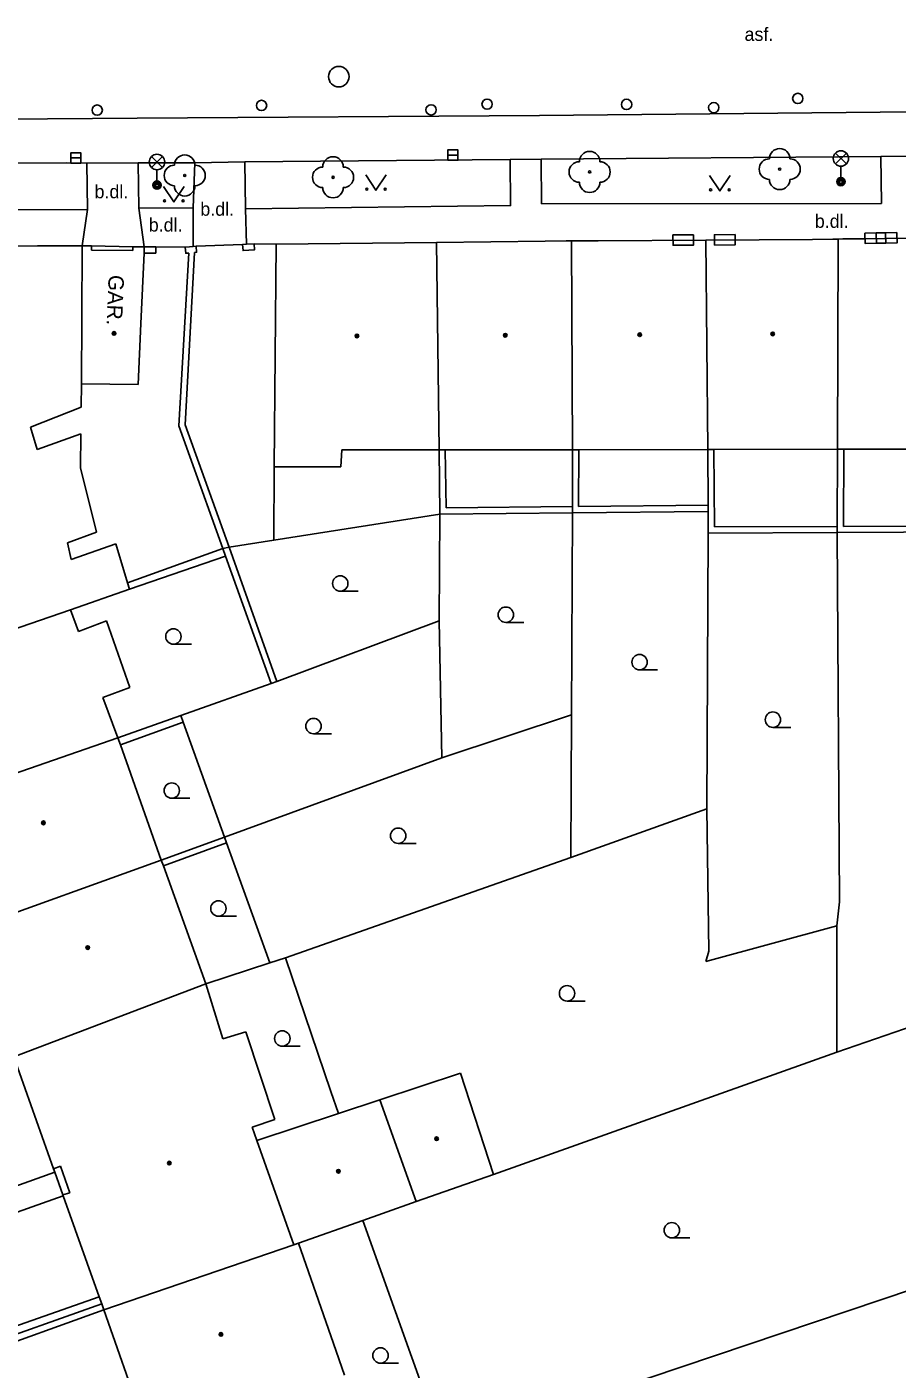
# Model space of a CAD drawing. Extents: x -596229 to -595156, y -1161237 to -1159376.
# Drawn here: x -595936.1 to -595893.7, y -1160957.9 to -1160892.5 of the extents above; entities that cross this region are included whole.
import ezdxf

# ---------------------------------------------------------------- set-up
doc = ezdxf.new("R2010")
doc.units = 0
for name, color, linetype in [('DOP - kresba z DSPS bez souradnic', 7, 'Continuous'), ('DOP - ploty', 7, 'Continuous'), ('DOP - rozhrani ploch obecne', 7, 'Continuous'), ('Level 22', 7, 'Continuous'), ('Level 24', 7, 'Continuous'), ('Level 27', 7, 'Continuous'), ('Level 28', 7, 'Continuous'), ('Level 33', 7, 'Continuous'), ('Level 36', 7, 'Continuous'), ('Level 39', 7, 'Continuous'), ('TM - budovy zdene_ betonove - NP', 7, 'Continuous'), ('TM - budovy zdene_ betonove - VP', 7, 'Continuous'), ('TM - chodniky - VP', 7, 'Continuous'), ('TM - komunikace - VP', 7, 'Continuous'), ('TM - letecke snimky - pomocna linie', 7, 'Continuous'), ('TM - plot drateny_ kovovy - VP', 7, 'Continuous'), ('TM - podezdivka plotu - VP', 7, 'Continuous'), ('TM - popis objektu', 7, 'Continuous'), ('TM - popis povrchu', 7, 'Continuous'), ('TM - rozhrani ploch obecne - VP', 7, 'Continuous'), ('TM - vjezd na pozemek', 7, 'Continuous'), ('TM - vstup do budovy - zdene_ betonove', 7, 'Continuous'), ('TM - vstup do budovy - zdene_ betonove  - shora neviditelny', 7, 'Continuous')]:
    doc.layers.add(name, color=color, linetype=linetype)

msp = doc.modelspace()

# ---------------------------------------------------------------- linework, layer by layer
at = {"layer": 'DOP - kresba z DSPS bez souradnic'}
for points in [[(-595926.56, -1160917.92), (-595931.2, -1160919.6)], [(-595931.55, -1160927.48), (-595928.5, -1160926.38)], [(-595929.46, -1160933.38), (-595926.38, -1160932.26)]]:
    msp.add_lwpolyline(points, dxfattribs=at)
at = {"layer": 'DOP - ploty'}
for points in [[(-595903, -1160930.6), (-595909.62, -1160932.97)], [(-595902.91, -1160937.53), (-595903, -1160930.6)], [(-595909.62, -1160932.97), (-595923.51, -1160937.85)], [(-595896.67, -1160936.29), (-595903.05, -1160938.03)], [(-595896.68, -1160942.44), (-595896.67, -1160936.29)], [(-595923.51, -1160937.85), (-595924.27, -1160938.1)], [(-595903.05, -1160938.03), (-595902.91, -1160937.53)], [(-595924.27, -1160938.1), (-595927.39, -1160939.12)], [(-595896.68, -1160942.44), (-595913.39, -1160948.39)]]:
    msp.add_lwpolyline(points, dxfattribs=at)
at = {"layer": 'DOP - rozhrani ploch obecne'}
for points in [[(-595916, -1160916.25), (-595924.09, -1160917.53)], [(-595916, -1160916.25), (-595916.03, -1160921.45)], [(-595909.59, -1160926.02), (-595909.55, -1160916.19)], [(-595896.54, -1160935.13), (-595896.66, -1160917.15)], [(-595924.09, -1160917.53), (-595926.26, -1160917.87)], [(-595903, -1160930.6), (-595902.94, -1160917.18)], [(-595926.43, -1160918.3), (-595931.1, -1160919.91)], [(-595926.26, -1160917.87), (-595926.56, -1160917.92)], [(-595916.03, -1160921.45), (-595923.93, -1160924.4)], [(-595915.9, -1160928.12), (-595916.03, -1160921.45)], [(-595924.21, -1160924.5), (-595928.61, -1160926.06)], [(-595923.93, -1160924.4), (-595924.21, -1160924.5)], [(-595928.61, -1160926.06), (-595931.67, -1160927.14)], [(-595928.61, -1160926.06), (-595928.5, -1160926.38)], [(-595915.9, -1160928.12), (-595909.59, -1160926.02)], [(-595909.62, -1160932.97), (-595909.59, -1160926.02)], [(-595928.5, -1160926.38), (-595926.48, -1160931.98)], [(-595926.48, -1160931.98), (-595915.9, -1160928.12)], [(-595926.48, -1160931.98), (-595929.56, -1160933.1)], [(-595926.38, -1160932.26), (-595926.48, -1160931.98)], [(-595924.27, -1160938.1), (-595926.38, -1160932.26)], [(-595896.67, -1160936.29), (-595896.54, -1160935.13)], [(-595921.3, -1160944.36), (-595923.51, -1160937.85)], [(-595896.68, -1160942.44), (-595890.09, -1160940.17)], [(-595920.94, -1160945.43), (-595921.3, -1160944.36)], [(-595915.78, -1160961.75), (-595919.75, -1160950.64)], [(-595889.72, -1160952.88), (-595909.04, -1160959.39)]]:
    msp.add_lwpolyline(points, dxfattribs=at)
at = {"layer": 'Level 22'}
for centre in [(-595899.46, -1160899.46), (-595928.42, -1160899.77), (-595921.2, -1160899.86), (-595908.71, -1160899.6)]:
    msp.add_circle(centre, 0.05, dxfattribs=at)
for centre, start, end in [((-595928.42, -1160899.27), 0, 180), ((-595921.2, -1160899.36), 0, 180), ((-595908.71, -1160899.1), 0, 180), ((-595899.46, -1160898.96), 0, 180), ((-595928.92, -1160899.77), 90, 270), ((-595927.92, -1160899.77), 270, 90), ((-595921.7, -1160899.86), 90, 270), ((-595920.7, -1160899.86), 270, 90), ((-595909.21, -1160899.6), 90, 270), ((-595908.21, -1160899.6), 270, 90), ((-595899.96, -1160899.46), 90, 270), ((-595898.96, -1160899.46), 270, 90), ((-595908.71, -1160900.1), 180, 0), ((-595899.46, -1160899.96), 180, 0), ((-595928.42, -1160900.27), 180, 0), ((-595921.2, -1160900.36), 180, 0)]:
    msp.add_arc(centre, 0.5, start, end, dxfattribs=at)
at = {"layer": 'Level 24'}
for points in [[(-595903.653, -1160902.658), (-595904.653, -1160902.664), (-595904.65, -1160903.164), (-595903.65, -1160903.158)], [(-595901.634, -1160902.647), (-595902.634, -1160902.655), (-595902.63, -1160903.155), (-595901.63, -1160903.147)], [(-595894.307, -1160902.565), (-595895.307, -1160902.58), (-595895.299, -1160903.08), (-595894.299, -1160903.065)], [(-595893.756, -1160902.553), (-595894.756, -1160902.569), (-595894.748, -1160903.069), (-595893.748, -1160903.053)]]:
    msp.add_lwpolyline(points, close=True, dxfattribs=at)
at = {"layer": 'Level 27'}
for p, q in [((-595915.62, -1160898.78), (-595915.12, -1160898.78)), ((-595933.97, -1160898.92), (-595933.47, -1160898.92))]:
    msp.add_line(p, q, dxfattribs=at)
for points in [[(-595933.97, -1160899.17), (-595933.47, -1160899.17), (-595933.47, -1160898.67), (-595933.97, -1160898.67)], [(-595915.62, -1160899.03), (-595915.12, -1160899.03), (-595915.12, -1160898.53), (-595915.62, -1160898.53)]]:
    msp.add_lwpolyline(points, close=True, dxfattribs=at)
msp.add_circle((-595920.92, -1160894.96), 0.5, dxfattribs=at)
at = {"layer": 'Level 28'}
for centre in [(-595924.68, -1160896.36), (-595913.7, -1160896.3), (-595906.91, -1160896.31), (-595902.67, -1160896.47), (-595898.58, -1160896.02), (-595932.68, -1160896.59), (-595916.43, -1160896.58)]:
    msp.add_circle(centre, 0.25, dxfattribs=at)
at = {"layer": 'Level 33'}
for p, q in [((-595930.035, -1160899.38), (-595929.505, -1160898.85)), ((-595930.035, -1160898.85), (-595929.505, -1160899.38)), ((-595896.745, -1160899.21), (-595896.215, -1160898.68)), ((-595896.745, -1160898.68), (-595896.215, -1160899.21)), ((-595929.77, -1160899.49), (-595929.77, -1160900.24)), ((-595896.48, -1160899.32), (-595896.48, -1160900.07))]:
    msp.add_line(p, q, dxfattribs=at)
for centre, radius in [((-595929.77, -1160899.115), 0.375), ((-595896.48, -1160898.945), 0.375), ((-595929.77, -1160900.24), 0.2), ((-595929.77, -1160900.24), 0.145), ((-595929.77, -1160900.24), 0.0876), ((-595896.48, -1160900.07), 0.2), ((-595896.48, -1160900.07), 0.145), ((-595896.48, -1160900.07), 0.0876)]:
    msp.add_circle(centre, radius, dxfattribs=at)
at = {"layer": 'Level 36'}
for p, q in [((-595920.85, -1160920.005), (-595919.975, -1160920.005)), ((-595912.79, -1160921.525), (-595911.915, -1160921.525)), ((-595928.97, -1160922.585), (-595928.095, -1160922.585)), ((-595906.28, -1160923.835), (-595905.405, -1160923.835)), ((-595922.15, -1160926.945), (-595921.275, -1160926.945)), ((-595899.79, -1160926.635), (-595898.915, -1160926.635)), ((-595929.05, -1160930.085), (-595928.175, -1160930.085)), ((-595918.03, -1160932.285), (-595917.155, -1160932.285)), ((-595926.78, -1160935.825), (-595925.905, -1160935.825)), ((-595909.81, -1160939.955), (-595908.935, -1160939.955)), ((-595923.67, -1160942.155), (-595922.795, -1160942.155)), ((-595904.71, -1160951.485), (-595903.835, -1160951.485)), ((-595918.89, -1160957.585), (-595918.015, -1160957.585))]:
    msp.add_line(p, q, dxfattribs=at)
for points in [[(-595919.61, -1160899.74), (-595919.11, -1160900.49), (-595918.61, -1160899.74)], [(-595902.87, -1160899.77), (-595902.37, -1160900.52), (-595901.87, -1160899.77)], [(-595929.45, -1160900.31), (-595928.95, -1160901.06), (-595928.45, -1160900.31)]]:
    msp.add_lwpolyline(points, dxfattribs=at)
for centre, radius in [((-595919.56, -1160900.44), 0.05), ((-595918.661, -1160900.44), 0.05), ((-595902.82, -1160900.47), 0.05), ((-595901.921, -1160900.47), 0.05), ((-595929.4, -1160901.01), 0.05), ((-595928.501, -1160901.01), 0.05), ((-595920.85, -1160919.63), 0.375), ((-595912.79, -1160921.15), 0.375), ((-595928.97, -1160922.21), 0.375), ((-595906.28, -1160923.46), 0.375), ((-595922.15, -1160926.57), 0.375), ((-595899.79, -1160926.26), 0.375), ((-595929.05, -1160929.71), 0.375), ((-595918.03, -1160931.91), 0.375), ((-595926.78, -1160935.45), 0.375), ((-595909.81, -1160939.58), 0.375), ((-595923.67, -1160941.78), 0.375), ((-595904.71, -1160951.11), 0.375), ((-595918.89, -1160957.21), 0.375)]:
    msp.add_circle(centre, radius, dxfattribs=at)
at = {"layer": 'Level 39'}
for centre, radius in [((-595931.86, -1160907.46), 0.09), ((-595931.86, -1160907.46), 0.0398), ((-595920.04, -1160907.58), 0.09), ((-595920.04, -1160907.58), 0.0398), ((-595912.82, -1160907.55), 0.09), ((-595912.82, -1160907.55), 0.0398), ((-595906.27, -1160907.52), 0.09), ((-595906.27, -1160907.52), 0.0398), ((-595899.8, -1160907.48), 0.09), ((-595899.8, -1160907.48), 0.0398), ((-595935.3, -1160931.28), 0.09), ((-595935.3, -1160931.28), 0.0398), ((-595933.14, -1160937.35), 0.09), ((-595933.14, -1160937.35), 0.0398), ((-595916.16, -1160946.66), 0.09), ((-595916.16, -1160946.66), 0.0398), ((-595929.17, -1160947.84), 0.09), ((-595929.17, -1160947.84), 0.0398), ((-595920.94, -1160948.24), 0.09), ((-595920.94, -1160948.24), 0.0398), ((-595926.66, -1160956.18), 0.09), ((-595926.66, -1160956.18), 0.0398)]:
    msp.add_circle(centre, radius, dxfattribs=at)
at = {"layer": 'TM - budovy zdene_ betonove - NP'}
for points in [[(-595932.95, -1160903.2), (-595932.95, -1160903.41)], [(-595930.94, -1160903.42), (-595930.94, -1160903.24)], [(-595934.47, -1160948), (-595934.8, -1160948.12)], [(-595934.02, -1160949.29), (-595934.47, -1160948)], [(-595934.02, -1160949.29), (-595934.35, -1160949.39)]]:
    msp.add_lwpolyline(points, dxfattribs=at)
at = {"layer": 'TM - budovy zdene_ betonove - VP'}
for points in [[(-595895.33, -1160902.85), (-595890.07, -1160902.77)], [(-595942.44, -1160903.23), (-595935.58, -1160903.2)], [(-595935.58, -1160903.2), (-595934.62, -1160903.2)], [(-595934.62, -1160903.2), (-595933.42, -1160903.19)], [(-595933.42, -1160903.19), (-595933.43, -1160906.67)], [(-595933.42, -1160903.19), (-595932.95, -1160903.2)], [(-595932.95, -1160903.2), (-595930.94, -1160903.24)], [(-595930.94, -1160903.24), (-595930.39, -1160903.25)], [(-595930.39, -1160903.25), (-595930.4, -1160903.55)], [(-595924.06, -1160913.96), (-595923.97, -1160903.12)], [(-595923.97, -1160903.12), (-595916.16, -1160903.03)], [(-595916.16, -1160903.03), (-595910.88, -1160902.97)], [(-595916.16, -1160903.03), (-595916.04, -1160913.12)], [(-595909.86, -1160902.96), (-595909.59, -1160902.96)], [(-595909.59, -1160902.96), (-595909.55, -1160913.12)], [(-595909.59, -1160902.96), (-595909.34, -1160902.96)], [(-595908.3, -1160902.95), (-595903.06, -1160902.92)], [(-595903.06, -1160902.92), (-595897.86, -1160902.88)], [(-595902.96, -1160913.11), (-595903.06, -1160902.92)], [(-595896.87, -1160902.87), (-595896.62, -1160902.87)], [(-595896.62, -1160902.87), (-595896.64, -1160913.1)], [(-595896.62, -1160902.87), (-595896.38, -1160902.86)], [(-595930.4, -1160903.55), (-595930.56, -1160906.98)], [(-595933.43, -1160906.67), (-595933.45, -1160909.91)], [(-595930.56, -1160906.98), (-595930.69, -1160909.94)], [(-595933.45, -1160909.91), (-595933.46, -1160911.05)], [(-595930.69, -1160909.94), (-595933.45, -1160909.91)], [(-595933.46, -1160911.05), (-595935.93, -1160912.02)], [(-595935.93, -1160912.02), (-595935.6, -1160913.11)], [(-595935.6, -1160913.11), (-595933.48, -1160912.35)], [(-595933.48, -1160912.35), (-595933.49, -1160914)], [(-595920.77, -1160913.13), (-595920.82, -1160913.96)], [(-595916.04, -1160913.12), (-595920.77, -1160913.13)], [(-595915.74, -1160913.12), (-595916.04, -1160913.12)], [(-595909.55, -1160913.12), (-595915.74, -1160913.12)], [(-595909.23, -1160913.12), (-595909.55, -1160913.12)], [(-595902.96, -1160913.11), (-595909.23, -1160913.12)], [(-595902.66, -1160913.11), (-595902.96, -1160913.11)], [(-595896.64, -1160913.1), (-595902.66, -1160913.11)], [(-595896.34, -1160913.1), (-595896.64, -1160913.1)], [(-595890.18, -1160913.09), (-595896.34, -1160913.1)], [(-595933.49, -1160914), (-595932.72, -1160917.14)], [(-595920.82, -1160913.96), (-595924.06, -1160913.96)], [(-595932.72, -1160917.14), (-595934.12, -1160917.65)], [(-595934.12, -1160917.65), (-595933.94, -1160918.46)], [(-595933.94, -1160918.46), (-595931.78, -1160917.7)], [(-595931.78, -1160917.7), (-595931.2, -1160919.6)], [(-595931.2, -1160919.6), (-595931.1, -1160919.91)], [(-595931.1, -1160919.91), (-595933.98, -1160920.91)], [(-595933.98, -1160920.91), (-595943.32, -1160924.13)], [(-595933.98, -1160920.91), (-595933.59, -1160921.96)], [(-595933.59, -1160921.96), (-595932.22, -1160921.45)], [(-595932.22, -1160921.45), (-595931.09, -1160924.7)], [(-595931.09, -1160924.7), (-595932.4, -1160925.18)], [(-595932.4, -1160925.18), (-595931.67, -1160927.14)], [(-595931.67, -1160927.14), (-595941.09, -1160930.4)], [(-595931.67, -1160927.14), (-595931.55, -1160927.48)], [(-595931.55, -1160927.48), (-595929.56, -1160933.1)], [(-595929.56, -1160933.1), (-595938.94, -1160936.48)], [(-595929.56, -1160933.1), (-595929.46, -1160933.38)], [(-595929.46, -1160933.38), (-595927.39, -1160939.12)], [(-595936.74, -1160942.67), (-595927.39, -1160939.12)], [(-595927.39, -1160939.12), (-595926.57, -1160941.8)], [(-595926.57, -1160941.8), (-595925.44, -1160941.46)], [(-595925.44, -1160941.46), (-595924.04, -1160945.72)], [(-595934.8, -1160948.12), (-595936.74, -1160942.67)], [(-595918.92, -1160944.76), (-595915, -1160943.47)], [(-595915, -1160943.47), (-595913.39, -1160948.39)], [(-595920.94, -1160945.43), (-595918.92, -1160944.76)], [(-595917.16, -1160949.72), (-595918.92, -1160944.76)], [(-595924.04, -1160945.72), (-595925.14, -1160946.1)], [(-595924.91, -1160946.75), (-595920.94, -1160945.43)], [(-595925.14, -1160946.1), (-595924.91, -1160946.75)], [(-595924.91, -1160946.75), (-595923.11, -1160951.82)], [(-595934.74, -1160948.28), (-595934.8, -1160948.12)], [(-595934.35, -1160949.39), (-595934.74, -1160948.28)], [(-595913.39, -1160948.39), (-595917.16, -1160949.72)], [(-595934.33, -1160949.44), (-595934.35, -1160949.39)], [(-595932.58, -1160954.36), (-595934.33, -1160949.44)], [(-595917.16, -1160949.72), (-595918.8, -1160950.3), (-595919.75, -1160950.64)], [(-595919.75, -1160950.64), (-595922.88, -1160951.74)], [(-595922.88, -1160951.74), (-595923.11, -1160951.82)], [(-595922.88, -1160951.74), (-595921.18, -1160956.63), (-595920.65, -1160958.16)], [(-595923.11, -1160951.82), (-595932.36, -1160954.98)], [(-595932.46, -1160954.7), (-595932.58, -1160954.36)], [(-595932.36, -1160954.98), (-595932.46, -1160954.7)], [(-595930.49, -1160960.3), (-595932.36, -1160954.98)]]:
    msp.add_lwpolyline(points, dxfattribs=at)
at = {"layer": 'TM - chodniky - VP'}
for points in [[(-595894.53, -1160898.84), (-595894.51, -1160901.13), (-595911.05, -1160901.15), (-595911.07, -1160898.98)], [(-595933.16, -1160901.42), (-595942.46, -1160901.45), (-595942.47, -1160899.2)], [(-595933.18, -1160899.17), (-595933.16, -1160901.42)], [(-595930.66, -1160901.37), (-595930.69, -1160899.15)], [(-595927.93, -1160899.16), (-595928.01, -1160901.34)], [(-595925.46, -1160901.4), (-595925.49, -1160899.11)], [(-595912.58, -1160899), (-595912.56, -1160901.24), (-595925.46, -1160901.4)], [(-595928.01, -1160901.34), (-595930.66, -1160901.37)], [(-595934.74, -1160948.28), (-595940.95, -1160950.51)], [(-595940.85, -1160951.74), (-595934.33, -1160949.44)]]:
    msp.add_lwpolyline(points, dxfattribs=at)
at = {"layer": 'TM - komunikace - VP'}
for points in [[(-595894.53, -1160898.84), (-595911.07, -1160898.98)], [(-595893.06, -1160898.83), (-595894.53, -1160898.84)], [(-595933.18, -1160899.17), (-595934.17, -1160899.15), (-595942.47, -1160899.2)], [(-595930.69, -1160899.15), (-595933.18, -1160899.17)], [(-595927.93, -1160899.16), (-595930.69, -1160899.15)], [(-595925.49, -1160899.11), (-595927.93, -1160899.16)], [(-595912.58, -1160899), (-595925.49, -1160899.11)], [(-595911.07, -1160898.98), (-595912.58, -1160899)]]:
    msp.add_lwpolyline(points, dxfattribs=at)
at = {"layer": 'TM - letecke snimky - pomocna linie'}
msp.add_lwpolyline([(-595924.06, -1160913.96), (-595924.09, -1160917.53)], dxfattribs=at)
at = {"layer": 'TM - plot drateny_ kovovy - VP'}
for points in [[(-595930.4, -1160903.55), (-595929.83, -1160903.55), (-595929.83, -1160903.25)], [(-595928.4, -1160903.26), (-595928.37, -1160903.56), (-595928.22, -1160903.55)], [(-595927.94, -1160903.52), (-595927.84, -1160903.51), (-595927.87, -1160903.21)], [(-595925.6, -1160903.13), (-595925.58, -1160903.43), (-595925.02, -1160903.39), (-595925.04, -1160903.09)], [(-595926.26, -1160917.87), (-595928.4, -1160911.91), (-595927.94, -1160903.52)], [(-595915.7, -1160915.95), (-595915.74, -1160913.12)], [(-595909.25, -1160915.88), (-595909.23, -1160913.12)], [(-595902.64, -1160916.88), (-595902.66, -1160913.11)], [(-595896.36, -1160916.85), (-595896.34, -1160913.1)], [(-595902.94, -1160915.82), (-595909.25, -1160915.88)], [(-595909.55, -1160915.89), (-595915.7, -1160915.95)], [(-595896.66, -1160916.85), (-595902.64, -1160916.88)], [(-595890.21, -1160916.82), (-595896.36, -1160916.85)], [(-595923.93, -1160924.4), (-595926.26, -1160917.87)], [(-595932.46, -1160954.7), (-595938.69, -1160956.9), (-595938.73, -1160956.8), (-595939.07, -1160956.92)]]:
    msp.add_lwpolyline(points, dxfattribs=at)
at = {"layer": 'TM - podezdivka plotu - VP'}
for points in [[(-595930.39, -1160903.25), (-595929.83, -1160903.25)], [(-595928.4, -1160903.26), (-595928.19, -1160903.24)], [(-595928.19, -1160903.24), (-595928.01, -1160903.22)], [(-595928.01, -1160903.22), (-595927.87, -1160903.21)], [(-595925.6, -1160903.13), (-595925.42, -1160903.12)], [(-595925.42, -1160903.12), (-595925.04, -1160903.09)], [(-595928.7, -1160911.95), (-595928.22, -1160903.55)], [(-595926.56, -1160917.92), (-595928.7, -1160911.95)], [(-595916.04, -1160913.12), (-595916, -1160916.25)], [(-595909.55, -1160913.12), (-595909.55, -1160915.89)], [(-595902.94, -1160915.82), (-595902.96, -1160913.11)], [(-595896.64, -1160913.1), (-595896.66, -1160916.85)], [(-595902.94, -1160916.12), (-595902.94, -1160915.82)], [(-595909.55, -1160916.19), (-595916, -1160916.25)], [(-595909.55, -1160915.89), (-595909.55, -1160916.19)], [(-595909.55, -1160916.19), (-595902.94, -1160916.12)], [(-595902.94, -1160917.18), (-595902.94, -1160916.12)], [(-595896.66, -1160917.15), (-595902.94, -1160917.18)], [(-595896.66, -1160916.85), (-595896.66, -1160917.15)], [(-595890.21, -1160917.12), (-595896.66, -1160917.15)], [(-595926.43, -1160918.3), (-595926.56, -1160917.92)], [(-595924.21, -1160924.5), (-595926.43, -1160918.3)], [(-595939.16, -1160956.65), (-595932.58, -1160954.36)], [(-595932.36, -1160954.98), (-595938.58, -1160957.23)]]:
    msp.add_lwpolyline(points, dxfattribs=at)
at = {"layer": 'TM - rozhrani ploch obecne - VP'}
for points in [[(-595844.51, -1160896.26), (-595853.96, -1160896.28), (-595873.2, -1160896.54), (-595892.92, -1160896.68), (-595911.15, -1160896.85), (-595930.74, -1160896.98), (-595952.54, -1160897.14), (-595957.11, -1160897.16)], [(-595933.42, -1160903.19), (-595933.16, -1160901.42)], [(-595930.39, -1160903.25), (-595930.66, -1160901.37)], [(-595928.01, -1160903.22), (-595928.01, -1160901.34)], [(-595925.42, -1160903.12), (-595925.46, -1160901.4)]]:
    msp.add_lwpolyline(points, dxfattribs=at)
at = {"layer": 'TM - vjezd na pozemek'}
for points in [[(-595928.4, -1160903.26), (-595929.83, -1160903.25)], [(-595925.6, -1160903.13), (-595927.87, -1160903.21)], [(-595923.97, -1160903.12), (-595925.04, -1160903.09)]]:
    msp.add_lwpolyline(points, dxfattribs=at)
at = {"layer": 'TM - vstup do budovy - zdene_ betonove'}
for points in [[(-595909.86, -1160902.96), (-595910.88, -1160902.97)], [(-595908.3, -1160902.95), (-595909.34, -1160902.96)], [(-595896.87, -1160902.87), (-595897.86, -1160902.88)], [(-595895.33, -1160902.85), (-595896.38, -1160902.86)]]:
    msp.add_lwpolyline(points, dxfattribs=at)
at = {"layer": 'TM - vstup do budovy - zdene_ betonove  - shora neviditelny'}
msp.add_lwpolyline([(-595930.94, -1160903.42), (-595932.95, -1160903.41)], dxfattribs=at)

# ---------------------------------------------------------------- texts
at = {"layer": 'TM - popis objektu'}
msp.add_text('GAR.', height=0.75, rotation=267.59, dxfattribs=at).set_placement((-595932.12, -1160904.6))
at = {"layer": 'TM - popis povrchu'}
for s, p in [('asf.', (-595901.17, -1160893.22)), ('b.dl.', (-595932.81, -1160900.88)), ('b.dl.', (-595927.66, -1160901.73)), ('b.dl.', (-595930.17, -1160902.5)), ('b.dl.', (-595897.75, -1160902.32))]:
    msp.add_text(s, height=0.65, dxfattribs=at).set_placement(p)

doc.saveas('drawing.dxf')
